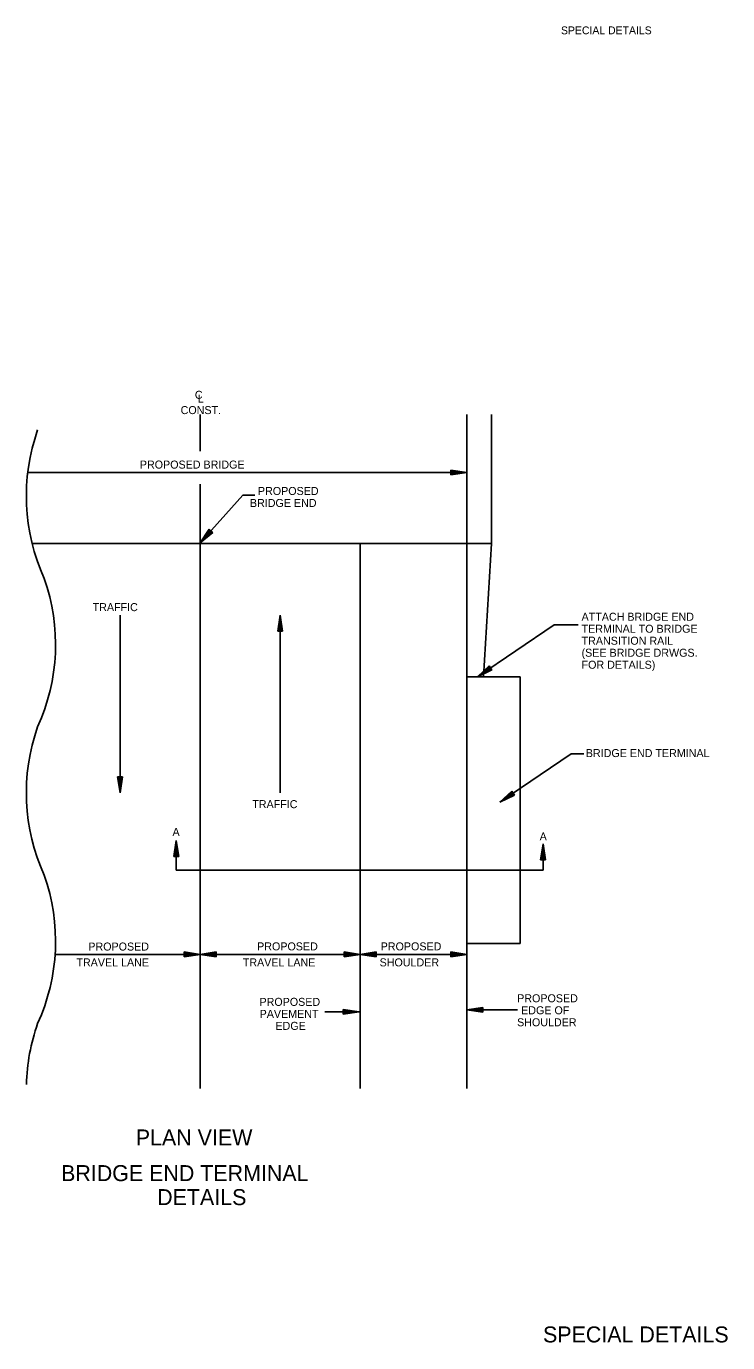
# Model space of a CAD drawing. Extents: x 1929624 to 1935547, y 596315 to 605721.
# Drawn here: x 1933758 to 1934284, y 604034 to 605022 of the extents above; entities that cross this region are included whole.
import ezdxf

# ---------------------------------------------------------------- set-up
doc = ezdxf.new("R2010")
doc.units = 0
for name, color, linetype in [('Default', 7, 'Continuous'), ('R_Border', 7, 'Continuous'), ('R_Border Prem', 7, 'Continuous')]:
    doc.layers.add(name, color=color, linetype=linetype)

msp = doc.modelspace()

# ---------------------------------------------------------------- linework, layer by layer
at = {"layer": 'Default'}
for p, q in [((1933888.68, 604730.58), (1933888.68, 604702.97)), ((1934088.68, 604730.58), (1934088.68, 604633.78)), ((1934107.01, 604730.58), (1934107.01, 604633.78)), ((1933759.51, 604687.01), (1934088.68, 604687.01)), ((1934076.68, 604688.81), (1934088.68, 604687.01)), ((1934076.68, 604688.81), (1934076.68, 604685.21)), ((1934076.68, 604688.51), (1934086.68, 604687.01)), ((1934076.68, 604688.2), (1934084.61, 604687.01)), ((1934076.68, 604687.9), (1934082.61, 604687.01)), ((1934076.68, 604687.59), (1934080.58, 604687.01)), ((1934076.68, 604687.29), (1934078.58, 604687.01)), ((1934076.68, 604685.21), (1934088.68, 604687.01)), ((1934076.68, 604686.42), (1934080.58, 604687.01)), ((1934076.68, 604685.82), (1934084.61, 604687.01)), ((1934076.68, 604685.51), (1934086.68, 604687.01)), ((1934076.68, 604686.12), (1934082.61, 604687.01)), ((1934076.68, 604686.73), (1934078.58, 604687.01)), ((1933888.68, 604678.42), (1933888.68, 604225.03)), ((1933888.8, 604634.35), (1933920.68, 604670.13)), ((1933920.68, 604670.13), (1933929.72, 604670.15)), ((1933895.44, 604644.51), (1933888.8, 604634.35)), ((1933898.13, 604642.11), (1933888.8, 604634.35)), ((1933895.66, 604644.31), (1933890.13, 604635.85)), ((1933897.9, 604642.31), (1933890.13, 604635.85)), ((1933895.89, 604644.1), (1933891.51, 604637.39)), ((1933897.67, 604642.52), (1933891.51, 604637.39)), ((1933896.12, 604643.9), (1933892.84, 604638.88)), ((1933897.45, 604642.71), (1933892.84, 604638.88)), ((1933896.34, 604643.7), (1933894.19, 604640.4)), ((1933897.22, 604642.92), (1933894.19, 604640.4)), ((1933898.13, 604642.11), (1933895.44, 604644.51)), ((1933896.57, 604643.5), (1933895.52, 604641.89)), ((1933896.99, 604643.12), (1933895.52, 604641.89)), ((1933762.82, 604633.78), (1934107.01, 604633.78)), ((1934008.68, 604633.78), (1934008.68, 604225.03)), ((1934088.68, 604633.78), (1934088.68, 604533.78)), ((1934101.18, 604533.78), (1934107.01, 604633.78)), ((1933828.68, 604579.96), (1933828.68, 604446.85)), ((1933946.88, 604567.96), (1933948.68, 604579.96)), ((1933947.18, 604567.96), (1933948.68, 604577.96)), ((1933947.49, 604567.96), (1933948.68, 604575.89)), ((1933947.79, 604567.96), (1933948.68, 604573.89)), ((1933948.1, 604567.96), (1933948.68, 604571.86)), ((1933948.68, 604579.96), (1933948.68, 604446.85)), ((1933950.48, 604567.96), (1933948.68, 604579.96)), ((1933950.18, 604567.96), (1933948.68, 604577.96)), ((1933949.87, 604567.96), (1933948.68, 604575.89)), ((1933949.57, 604567.96), (1933948.68, 604573.89)), ((1933949.27, 604567.96), (1933948.68, 604571.86)), ((1934096.5, 604533.9), (1934154.01, 604572.89)), ((1934154.01, 604572.89), (1934172.1, 604572.89)), ((1933946.88, 604567.96), (1933950.48, 604567.96)), ((1933948.4, 604567.96), (1933948.68, 604569.86)), ((1933948.96, 604567.96), (1933948.68, 604569.86)), ((1934105.42, 604542.12), (1934096.5, 604533.9)), ((1934107.44, 604539.14), (1934105.42, 604542.12)), ((1934088.65, 604533.78), (1934088.65, 604333.78)), ((1934088.68, 604535.95), (1934088.68, 604225.03)), ((1934088.68, 604533.78), (1934128.72, 604533.78)), ((1934107.44, 604539.14), (1934096.5, 604533.9)), ((1934105.59, 604541.88), (1934098.16, 604535.02)), ((1934107.27, 604539.39), (1934098.16, 604535.02)), ((1934105.76, 604541.62), (1934099.87, 604536.18)), ((1934107.1, 604539.65), (1934099.87, 604536.18)), ((1934105.93, 604541.37), (1934101.52, 604537.3)), ((1934106.93, 604539.89), (1934101.52, 604537.3)), ((1934106.1, 604541.12), (1934103.2, 604538.45)), ((1934106.76, 604540.15), (1934103.2, 604538.45)), ((1934106.27, 604540.87), (1934104.86, 604539.57)), ((1934106.59, 604540.4), (1934104.86, 604539.57)), ((1934128.72, 604533.78), (1934128.72, 604333.78)), ((1934113.33, 604439.94), (1934166.94, 604476.13)), ((1934166.94, 604476.13), (1934176.4, 604476.2)), ((1933826.88, 604458.85), (1933828.68, 604446.85)), ((1933830.48, 604458.85), (1933826.88, 604458.85)), ((1933827.18, 604458.85), (1933828.68, 604448.85)), ((1933827.49, 604458.85), (1933828.68, 604450.92)), ((1933827.79, 604458.85), (1933828.68, 604452.92)), ((1933828.09, 604458.85), (1933828.68, 604454.95)), ((1933828.4, 604458.85), (1933828.68, 604456.95)), ((1933830.48, 604458.85), (1933828.68, 604446.85)), ((1933829.26, 604458.85), (1933828.68, 604454.95)), ((1933829.87, 604458.85), (1933828.68, 604450.92)), ((1933830.18, 604458.85), (1933828.68, 604448.85)), ((1933829.57, 604458.85), (1933828.68, 604452.92)), ((1933828.96, 604458.85), (1933828.68, 604456.95)), ((1934122.27, 604448.15), (1934113.33, 604439.94)), ((1934124.28, 604445.16), (1934113.33, 604439.94)), ((1934122.44, 604447.9), (1934114.99, 604441.06)), ((1934124.12, 604445.41), (1934114.99, 604441.06)), ((1934122.61, 604447.64), (1934116.7, 604442.22)), ((1934123.94, 604445.66), (1934116.7, 604442.22)), ((1934122.78, 604447.4), (1934118.36, 604443.33)), ((1934123.78, 604445.91), (1934118.36, 604443.33)), ((1934122.95, 604447.14), (1934120.04, 604444.47)), ((1934123.6, 604446.17), (1934120.04, 604444.47)), ((1934123.12, 604446.89), (1934121.7, 604445.59)), ((1934123.43, 604446.42), (1934121.7, 604445.59)), ((1934124.28, 604445.16), (1934122.27, 604448.15)), ((1933869.09, 604399.16), (1933870.89, 604411.16)), ((1933869.39, 604399.16), (1933870.89, 604409.16)), ((1933869.7, 604399.16), (1933870.89, 604407.09)), ((1933870, 604399.16), (1933870.89, 604405.09)), ((1933870.89, 604388.9), (1933870.89, 604411.16)), ((1933872.69, 604399.16), (1933870.89, 604411.16)), ((1933872.39, 604399.16), (1933870.89, 604409.16)), ((1933872.08, 604399.16), (1933870.89, 604407.09)), ((1933871.78, 604399.16), (1933870.89, 604405.09)), ((1934143.94, 604396.62), (1934145.74, 604408.62)), ((1934144.24, 604396.62), (1934145.74, 604406.62)), ((1934144.55, 604396.62), (1934145.74, 604404.55)), ((1934145.74, 604388.9), (1934145.74, 604408.62)), ((1934147.54, 604396.62), (1934145.74, 604408.62)), ((1934147.24, 604396.62), (1934145.74, 604406.62)), ((1934146.93, 604396.62), (1934145.74, 604404.55)), ((1933869.09, 604399.16), (1933872.69, 604399.16)), ((1933870.31, 604399.16), (1933870.89, 604403.06)), ((1933870.61, 604399.16), (1933870.89, 604401.06)), ((1933871.48, 604399.16), (1933870.89, 604403.06)), ((1933871.17, 604399.16), (1933870.89, 604401.06)), ((1934143.94, 604396.62), (1934147.54, 604396.62)), ((1934144.85, 604396.62), (1934145.74, 604402.55)), ((1934145.16, 604396.62), (1934145.74, 604400.52)), ((1934145.46, 604396.62), (1934145.74, 604398.52)), ((1934146.63, 604396.62), (1934145.74, 604402.55)), ((1934146.33, 604396.62), (1934145.74, 604400.52)), ((1934146.02, 604396.62), (1934145.74, 604398.52)), ((1933870.89, 604388.9), (1934145.74, 604388.9)), ((1933780.05, 604325.67), (1933888.68, 604325.67)), ((1933876.68, 604327.47), (1933888.68, 604325.67)), ((1933876.68, 604327.47), (1933876.68, 604323.87)), ((1933876.68, 604327.17), (1933886.68, 604325.67)), ((1933876.68, 604326.86), (1933884.61, 604325.67)), ((1933876.68, 604326.56), (1933882.61, 604325.67)), ((1933876.68, 604326.25), (1933880.58, 604325.67)), ((1933876.68, 604325.95), (1933878.58, 604325.67)), ((1933876.68, 604323.87), (1933888.68, 604325.67)), ((1933876.68, 604325.08), (1933880.58, 604325.67)), ((1933876.68, 604324.48), (1933884.61, 604325.67)), ((1933876.68, 604324.17), (1933886.68, 604325.67)), ((1933876.68, 604324.78), (1933882.61, 604325.67)), ((1933876.68, 604325.39), (1933878.58, 604325.67)), ((1933900.68, 604327.47), (1933888.68, 604325.67)), ((1933900.68, 604323.87), (1933888.68, 604325.67)), ((1933888.68, 604325.67), (1934008.68, 604325.67)), ((1933900.68, 604327.17), (1933890.68, 604325.67)), ((1933900.68, 604324.17), (1933890.68, 604325.67)), ((1933900.68, 604326.86), (1933892.75, 604325.67)), ((1933900.68, 604324.48), (1933892.75, 604325.67)), ((1933900.68, 604326.56), (1933894.75, 604325.67)), ((1933900.68, 604324.78), (1933894.75, 604325.67)), ((1933900.68, 604326.26), (1933896.78, 604325.67)), ((1933900.68, 604325.09), (1933896.78, 604325.67)), ((1933900.68, 604325.95), (1933898.78, 604325.67)), ((1933900.68, 604325.39), (1933898.78, 604325.67)), ((1933900.68, 604323.87), (1933900.68, 604327.47)), ((1933996.68, 604327.47), (1934008.68, 604325.67)), ((1933996.68, 604327.47), (1933996.68, 604323.87)), ((1933996.68, 604327.17), (1934006.68, 604325.67)), ((1933996.68, 604326.86), (1934004.61, 604325.67)), ((1933996.68, 604326.56), (1934002.61, 604325.67)), ((1933996.68, 604326.25), (1934000.58, 604325.67)), ((1933996.68, 604325.95), (1933998.58, 604325.67)), ((1933996.68, 604323.87), (1934008.68, 604325.67)), ((1933996.68, 604325.08), (1934000.58, 604325.67)), ((1933996.68, 604324.48), (1934004.61, 604325.67)), ((1933996.68, 604324.17), (1934006.68, 604325.67)), ((1933996.68, 604324.78), (1934002.61, 604325.67)), ((1933996.68, 604325.39), (1933998.58, 604325.67)), ((1934020.68, 604327.47), (1934008.68, 604325.67)), ((1934008.68, 604325.67), (1934088.68, 604325.67)), ((1934020.68, 604323.87), (1934008.68, 604325.67)), ((1934020.68, 604327.17), (1934010.68, 604325.67)), ((1934020.68, 604324.17), (1934010.68, 604325.67)), ((1934020.68, 604326.86), (1934012.75, 604325.67)), ((1934020.68, 604324.48), (1934012.75, 604325.67)), ((1934020.68, 604326.56), (1934014.75, 604325.67)), ((1934020.68, 604324.78), (1934014.75, 604325.67)), ((1934020.68, 604326.26), (1934016.78, 604325.67)), ((1934020.68, 604325.09), (1934016.78, 604325.67)), ((1934020.68, 604325.95), (1934018.78, 604325.67)), ((1934020.68, 604325.39), (1934018.78, 604325.67)), ((1934020.68, 604323.87), (1934020.68, 604327.47)), ((1934076.68, 604327.47), (1934088.68, 604325.67)), ((1934076.68, 604327.47), (1934076.68, 604323.87)), ((1934076.68, 604327.17), (1934086.68, 604325.67)), ((1934076.68, 604326.86), (1934084.61, 604325.67)), ((1934076.68, 604326.56), (1934082.61, 604325.67)), ((1934076.68, 604326.25), (1934080.58, 604325.67)), ((1934076.68, 604325.95), (1934078.58, 604325.67)), ((1934076.68, 604323.87), (1934088.68, 604325.67)), ((1934076.68, 604325.08), (1934080.58, 604325.67)), ((1934076.68, 604324.48), (1934084.61, 604325.67)), ((1934076.68, 604324.17), (1934086.68, 604325.67)), ((1934076.68, 604324.78), (1934082.61, 604325.67)), ((1934076.68, 604325.39), (1934078.58, 604325.67)), ((1934088.68, 604333.78), (1934128.72, 604333.78)), ((1934100.68, 604285.94), (1934088.68, 604284.14)), ((1934100.68, 604285.64), (1934090.68, 604284.14)), ((1934100.68, 604282.34), (1934100.68, 604285.94)), ((1933982.12, 604282.55), (1934007.97, 604282.55)), ((1933995.97, 604284.35), (1934007.97, 604282.55)), ((1933995.97, 604284.35), (1933995.97, 604280.75)), ((1933995.97, 604284.05), (1934005.97, 604282.55)), ((1933995.97, 604283.74), (1934003.9, 604282.55)), ((1933995.97, 604283.44), (1934001.9, 604282.55)), ((1933995.97, 604283.13), (1933999.87, 604282.55)), ((1933995.97, 604282.83), (1933997.87, 604282.55)), ((1933995.97, 604280.75), (1934007.97, 604282.55)), ((1933995.97, 604281.96), (1933999.87, 604282.55)), ((1933995.97, 604281.36), (1934003.9, 604282.55)), ((1933995.97, 604281.05), (1934005.97, 604282.55)), ((1933995.97, 604281.66), (1934001.9, 604282.55)), ((1933995.97, 604282.27), (1933997.87, 604282.55)), ((1934126.54, 604284.14), (1934088.68, 604284.14)), ((1934100.68, 604282.34), (1934088.68, 604284.14)), ((1934100.68, 604282.64), (1934090.68, 604284.14)), ((1934100.68, 604285.33), (1934092.75, 604284.14)), ((1934100.68, 604282.95), (1934092.75, 604284.14)), ((1934100.68, 604285.03), (1934094.75, 604284.14)), ((1934100.68, 604283.25), (1934094.75, 604284.14)), ((1934100.68, 604284.73), (1934096.78, 604284.14)), ((1934100.68, 604283.56), (1934096.78, 604284.14)), ((1934100.68, 604284.42), (1934098.78, 604284.14)), ((1934100.68, 604283.86), (1934098.78, 604284.14))]:
    msp.add_line(p, q, dxfattribs=at)
for centre, start, end in [((1933907.32, 604669.47), 160.57465, 204.52912), ((1933631.55, 604558.18), 335.47088, 19.42535), ((1933907.32, 604446.89), 160.57465, 204.52912), ((1933631.55, 604335.6), 335.47088, 19.42535), ((1933907.32, 604224.31), 160.57465, 178.55672)]:
    msp.add_arc(centre, 148.84, start, end, dxfattribs=at)

# ---------------------------------------------------------------- texts
for s, height, p in [('C', 6, (1933884.76, 604742.32)), ('L', 6, (1933886.87, 604739.5)), ('CONST.', 6, (1933874.13, 604730.87)), ('PROPOSED BRIDGE', 6, (1933843.56, 604690.01)), ('PROPOSED', 6, (1933932.05, 604670.21)), ('BRIDGE END', 6, (1933926.05, 604661.21)), ('TRAFFIC', 6, (1933808.18, 604583.1)), ('ATTACH BRIDGE END', 6, (1934174.63, 604575.9)), ('TERMINAL TO BRIDGE', 6, (1934174.63, 604566.9)), ('TRANSITION RAIL', 6, (1934174.63, 604557.9)), ('(SEE BRIDGE DRWGS.', 6, (1934174.63, 604548.9)), ('FOR DETAILS)', 6, (1934174.63, 604539.9)), ('BRIDGE END TERMINAL', 6, (1934177.8, 604473.65)), ('TRAFFIC', 6, (1933927.82, 604435.34)), ('A', 6, (1933868.03, 604414.54)), ('A', 6, (1934143.22, 604411.14)), ('PROPOSED', 6, (1933931.46, 604328.67)), ('PROPOSED', 6, (1934024.06, 604328.67)), ('PROPOSED', 6, (1933804.94, 604328.55)), ('TRAVEL LANE', 6, (1933796.02, 604316.67)), ('TRAVEL LANE', 6, (1933920.71, 604316.67)), ('SHOULDER', 6, (1934023.24, 604316.67)), ('PROPOSED', 6, (1934126.36, 604289.75)), ('PROPOSED', 6, (1933933.22, 604287.07)), ('EDGE OF', 6, (1934129.33, 604280.75)), ('PAVEMENT', 6, (1933933.33, 604278.07)), ('SHOULDER', 6, (1934126.29, 604271.75)), ('EDGE', 6, (1933945.17, 604269.07)), ('PLAN VIEW', 12, (1933840.5, 604182.36)), ('BRIDGE END TERMINAL', 12, (1933784.52, 604155.62)), ('DETAILS', 12, (1933856.52, 604137.62))]:
    msp.add_text(s, height=height, rotation=360, dxfattribs=at).set_placement(p)
at = {"layer": 'R_Border'}
msp.add_text('SPECIAL DETAILS', height=12, rotation=360, dxfattribs=at).set_placement((1934145.73, 604034.64))
at = {"layer": 'R_Border Prem'}
msp.add_text('SPECIAL DETAILS', height=5.862, rotation=360, dxfattribs=at).set_placement((1934159.2, 605015.73))

doc.saveas('drawing.dxf')
